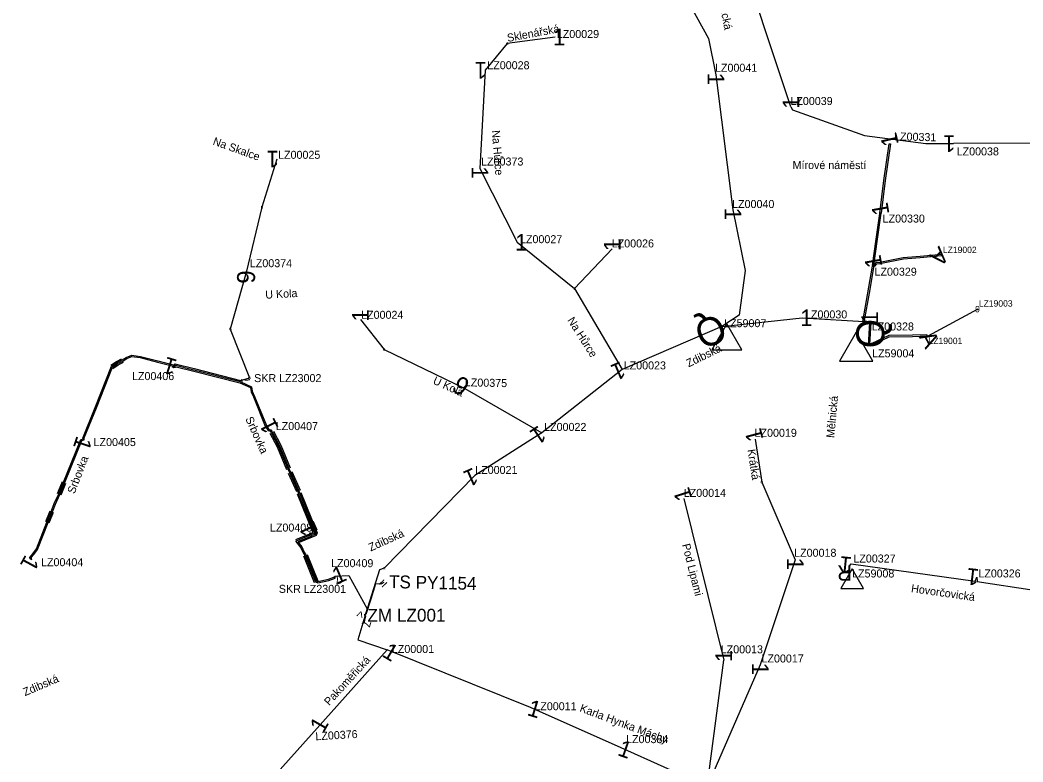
# Model space of a CAD drawing. Extents: x -736540 to -735418, y -1033000 to -1031598.
# Drawn here: x -736325 to -736011.7, y -1032340.8 to -1032109 of the extents above; entities that cross this region are included whole.
import ezdxf

# ---------------------------------------------------------------- set-up
doc = ezdxf.new("R2010")
doc.units = 0
for name, color, linetype in [('ftf_2010', 7, 'Continuous'), ('ftf_2020', 7, 'Continuous'), ('ftf_2050', 7, 'Continuous'), ('ftf_2060', 7, 'Continuous'), ('ftf_2080', 7, 'Continuous'), ('ftf_2140', 7, 'Continuous'), ('ftf_2240', 7, 'Continuous'), ('ftf_3010', 7, 'Continuous'), ('ftf_3010_ftf_3010_gtda_3015_gtda_3015_1', 7, 'Continuous'), ('ftf_3050', 7, 'Continuous'), ('ftf_3050_ftf_3050_gtda_3055_gtda_3055_1', 7, 'Continuous'), ('ftf_3060', 7, 'Continuous'), ('ftf_3060_ftf_3060_gtda_3065_gtda_3065_1', 7, 'Continuous'), ('ftf_3070', 7, 'Continuous'), ('ftf_3070_ftf_3070_gtda_3075_gtda_3075_1', 7, 'Continuous'), ('ftf_3150', 7, 'Continuous'), ('ftf_3150_ftf_3150_gtda_3155_gtda_3155_1', 7, 'Continuous'), ('ftf_3160', 7, 'Continuous'), ('ftf_3160_ftf_3160_gtda_3165_gtda_3165_1', 7, 'Continuous'), ('ftf_3170', 7, 'Continuous'), ('ftf_3170_ftf_3170_gtda_3175_gtda_3175_1', 7, 'Continuous'), ('ftf_3210', 7, 'Continuous'), ('ftf_3240', 7, 'Continuous'), ('ftf_3260', 7, 'Continuous'), ('ftf_3260_ftf_3260_gtda_3265_gtda_3265_1', 7, 'Continuous'), ('ftf_3270', 7, 'Continuous'), ('ftf_3270_ftf_3270_gtda_3275_gtda_3275_1', 7, 'Continuous'), ('ftf_nu', 7, 'Continuous')]:
    doc.layers.add(name, color=color, linetype=linetype)

msp = doc.modelspace()

# ---------------------------------------------------------------- linework, layer by layer
at = {"layer": 'ftf_2010'}
for points in [[(-736084.14, -1032136.1), (-736101.83, -1032082.79)], [(-736127.21, -1032098.34), (-736125.97, -1032099.2), (-736125.31, -1032100.78), (-736117.57, -1032100.74), (-736109.87, -1032114.77), (-736107.59, -1032126.1)], [(-736107.59, -1032126.1), (-736102.25, -1032168.26)], [(-736084.14, -1032136.1), (-736083.63, -1032137.03), (-736061.14, -1032145.09), (-736042.04, -1032147.61), (-736033.38, -1032147.59)], [(-735958.39, -1032137.2), (-735958.85, -1032137.46), (-735959.94, -1032142.82), (-735967.55, -1032142.1), (-735968.5, -1032152.08), (-735972.92, -1032151.65), (-736001.05, -1032147.52), (-736033.38, -1032147.59)], [(-736053.07, -1032147.7), (-736054.74, -1032159.15), (-736056, -1032169.35)], [(-736102.25, -1032168.26), (-736098.43, -1032187.26), (-736100.35, -1032201.22), (-736105.73, -1032204.76)], [(-736058.22, -1032185.7), (-736057.12, -1032177.49), (-736056, -1032169.35)], [(-736058.22, -1032185.7), (-736059.74, -1032194.3), (-736061.27, -1032202.9), (-736059.51, -1032203.25)], [(-736059.34, -1032210.76), (-736059.89, -1032210.72), (-736059.46, -1032203.51), (-736059.51, -1032203.25)], [(-736304.98, -1032240.11), (-736305.39, -1032239.62), (-736301.51, -1032230.04), (-736296.42, -1032217.19), (-736294.7, -1032216), (-736293.07, -1032215.19), (-736291.84, -1032214.41), (-736290.08, -1032213.75), (-736287.38, -1032214.07), (-736281.93, -1032215.51), (-736277.18, -1032216.68), (-736276.97, -1032217.56)], [(-736276.97, -1032217.56), (-736276.77, -1032216.69), (-736276.55, -1032216.42), (-736270.54, -1032217.9), (-736256.06, -1032221.58), (-736253.32, -1032220.8)], [(-736276.97, -1032217.56), (-736276.4, -1032216.87), (-736270.64, -1032218.28), (-736256.19, -1032221.96), (-736252.65, -1032223.55), (-736252.43, -1032224.99), (-736251.73, -1032226.58), (-736248.03, -1032235.72), (-736247.26, -1032236.91), (-736246.67, -1032237.03)], [(-736246.67, -1032237.03), (-736246.78, -1032237.56), (-736246.54, -1032237.86), (-736244.27, -1032242.2), (-736241.33, -1032249.25), (-736240.81, -1032250.37), (-736238.23, -1032256.18), (-736238.05, -1032256.88), (-736233.01, -1032269.24), (-736233.07, -1032269.4), (-736233.62, -1032269.62), (-736234.42, -1032269.21)], [(-736321.33, -1032277.6), (-736321.51, -1032276.96), (-736320.65, -1032275.97), (-736319.52, -1032274.37), (-736316.23, -1032265.98), (-736314.87, -1032262.64), (-736313.93, -1032260.22), (-736312.53, -1032257.21), (-736311.02, -1032253.51), (-736305.7, -1032240.38), (-736304.98, -1032240.11)], [(-736234.42, -1032269.21), (-736234.38, -1032269.94), (-736238.8, -1032271.78), (-736238.82, -1032271.9), (-736237.26, -1032273.84), (-736236.55, -1032275.41), (-736236.06, -1032276.24), (-736232.7, -1032284.52), (-736231.94, -1032284.87), (-736228.53, -1032284.05), (-736226.5, -1032283.37), (-736226.52, -1032282.73)], [(-736211.19, -1032280.26), (-736212.72, -1032280.76), (-736217.01, -1032294.65), (-736217.4, -1032294.8)], [(-736065.77, -1032279.38), (-736065.33, -1032278.91), (-736045.97, -1032281.62), (-736026.61, -1032284.33), (-736026.07, -1032283.1)], [(-736226.52, -1032282.73), (-736222.26, -1032282.58), (-736216.58, -1032292.94), (-736217.05, -1032294.51), (-736217.4, -1032294.8)], [(-736026.07, -1032283.1), (-736025.93, -1032284.39), (-736008.19, -1032287.1), (-735990.46, -1032289.82), (-735986.98, -1032291.47)], [(-736217.4, -1032294.8), (-736217.24, -1032295.33), (-736219.49, -1032302.63), (-736210.28, -1032305.75)]]:
    msp.add_lwpolyline(points, dxfattribs=at)
at = {"layer": 'ftf_2020'}
for points in [[(-736058.22, -1032185.7), (-736057.54, -1032184.73), (-736056.39, -1032184.64), (-736049.06, -1032183.17), (-736043.79, -1032182.77), (-736036.88, -1032182.1)], [(-736059.34, -1032210.76), (-736053.42, -1032207.93), (-736046.17, -1032207.85), (-736043.8, -1032207.79), (-736041.42, -1032207.73)]]:
    msp.add_lwpolyline(points, dxfattribs=at)
at = {"layer": 'ftf_2050'}
for points in [[(-736157.8, -1032114.33), (-736172.83, -1032116.38), (-736179.72, -1032124.69)], [(-736179.72, -1032124.69), (-736181.33, -1032155.34)], [(-736244.72, -1032152.46), (-736249.41, -1032167.46), (-736254.35, -1032187.85)], [(-736181.33, -1032155.34), (-736169.66, -1032178.44)], [(-736169.66, -1032178.44), (-736151.73, -1032192.91), (-736136.87, -1032218.15)], [(-736139.99, -1032180.53), (-736151.73, -1032192.91)], [(-736254.35, -1032187.85), (-736259.29, -1032205.53), (-736253.32, -1032220.8)], [(-736218.63, -1032202.55), (-736211.26, -1032211.91), (-736186.01, -1032224.1), (-736186.05, -1032224.11)], [(-736105.73, -1032204.76), (-736080.61, -1032202.02)], [(-736080.61, -1032202.02), (-736059.51, -1032203.25)], [(-736136.87, -1032218.15), (-736162, -1032237.98)], [(-736186.01, -1032224.1), (-736162, -1032237.98)], [(-736162, -1032237.98), (-736182.91, -1032251.34)], [(-736095.33, -1032239.95), (-736093.27, -1032253.41), (-736082.77, -1032277.61)], [(-736182.91, -1032251.34), (-736211.19, -1032280.26)], [(-736117.59, -1032258.43), (-736105.13, -1032308.95)], [(-736082.77, -1032277.61), (-736093.72, -1032310.39)], [(-736232.21, -1032330.19), (-736210.28, -1032305.75)], [(-736165.48, -1032323.8), (-736210.28, -1032305.75)], [(-736110.31, -1032348.41), (-736105.13, -1032308.95)], [(-736093.72, -1032310.39), (-736110.31, -1032348.41)], [(-736137.15, -1032336.37), (-736165.48, -1032323.8)], [(-736260.81, -1032362.16), (-736232.21, -1032330.19)], [(-736110.31, -1032348.41), (-736137.15, -1032336.37)]]:
    msp.add_lwpolyline(points, dxfattribs=at)
at = {"layer": 'ftf_2060'}
msp.add_lwpolyline([(-736211.38, -1032284.72), (-736212.22, -1032285.28), (-736213.9, -1032285.1), (-736215.4, -1032289.9), (-736216.91, -1032294.69), (-736217.4, -1032294.8), (-736217.04, -1032295.11), (-736217.6, -1032297.43), (-736218.24, -1032297.66)], dxfattribs=at)
at = {"layer": 'ftf_2080'}
for points in [[(-736025.8, -1032199.34), (-736041.42, -1032207.73)], [(-736105.73, -1032204.76), (-736136.87, -1032218.15)]]:
    msp.add_lwpolyline(points, dxfattribs=at)
at = {"layer": 'ftf_2140'}
for points in [[(-736059.51, -1032203.25), (-736059.59, -1032203.64), (-736061.73, -1032203.22), (-736058.65, -1032185.85), (-736058.24, -1032185.72), (-736058.61, -1032185.64), (-736057.52, -1032177.44), (-736056.42, -1032169.43), (-736056, -1032169.35), (-736056.4, -1032169.3), (-736055.13, -1032159.09), (-736053.46, -1032147.65), (-736053.07, -1032147.7)], [(-736058.22, -1032185.7), (-736057.89, -1032185.93), (-736057.32, -1032185.12), (-736056.34, -1032185.03), (-736049.01, -1032183.57), (-736043.76, -1032183.17), (-736037.06, -1032182.52), (-736036.88, -1032182.1)], [(-736041.42, -1032207.73), (-736041.68, -1032207.34), (-736046.18, -1032207.45), (-736053.51, -1032207.53), (-736059.07, -1032210.18), (-736059.34, -1032210.76), (-736059.42, -1032210.35), (-736059.47, -1032210.35), (-736059.05, -1032203.49), (-736059.12, -1032203.17), (-736059.51, -1032203.25)], [(-736321.33, -1032277.6), (-736321.82, -1032277.32), (-736321.95, -1032276.86), (-736320.97, -1032275.72), (-736319.87, -1032274.18), (-736316.6, -1032265.83), (-736315.24, -1032262.49), (-736314.29, -1032260.06), (-736312.89, -1032257.05), (-736311.39, -1032253.36), (-736306, -1032240.06), (-736305.54, -1032240), (-736304.98, -1032240.11), (-736304.93, -1032239.54), (-736301.14, -1032230.19), (-736296.09, -1032217.45), (-736294.5, -1032216.35), (-736292.87, -1032215.54), (-736291.66, -1032214.77), (-736290.03, -1032214.16), (-736287.45, -1032214.47), (-736282.03, -1032215.9), (-736277.51, -1032217.01), (-736277.45, -1032217.26), (-736276.97, -1032217.56), (-736276.41, -1032217.5), (-736276.25, -1032217.32), (-736270.74, -1032218.67), (-736256.32, -1032222.34), (-736253.01, -1032223.83), (-736252.81, -1032225.11), (-736252.1, -1032226.73), (-736248.39, -1032235.91), (-736247.5, -1032237.27), (-736247.14, -1032237.34), (-736246.67, -1032237.03), (-736246.32, -1032237.49), (-736246.21, -1032237.64), (-736243.91, -1032242.03), (-736240.96, -1032249.09), (-736240.44, -1032250.2), (-736237.85, -1032256.04), (-736237.67, -1032256.76), (-736232.58, -1032269.24), (-736232.76, -1032269.7), (-736233.64, -1032270.07), (-736233.98, -1032269.89), (-736233.96, -1032270.2), (-736238.25, -1032271.98), (-736236.92, -1032273.63), (-736236.19, -1032275.22), (-736235.7, -1032276.07), (-736232.39, -1032284.22), (-736231.9, -1032284.45), (-736228.64, -1032283.66), (-736226.96, -1032283.1), (-736226.52, -1032282.73)], [(-736233.98, -1032269.89), (-736234.42, -1032269.21)]]:
    msp.add_lwpolyline(points, dxfattribs=at)
at = {"layer": 'ftf_2240'}
for points in [[(-736108.82, -1032212.03), (-736099.47, -1032212.03), (-736104.14, -1032203.93)], [(-736068.96, -1032215.53), (-736058.57, -1032215.53), (-736063.77, -1032206.53)], [(-736068.57, -1032286.64), (-736061.44, -1032286.64), (-736065.01, -1032280.47)]]:
    msp.add_lwpolyline(points, close=True, dxfattribs=at)
at = {"layer": 'ftf_3210'}
for points in [[(-736296.65, -1032216.86), (-736294.9, -1032215.66), (-736293.24, -1032214.83)], [(-736295.96, -1032217.85), (-736294.29, -1032216.69), (-736292.71, -1032215.91)], [(-736246.9, -1032238.05), (-736244.64, -1032242.37), (-736241.7, -1032249.4)], [(-736245.83, -1032237.49), (-736243.55, -1032241.86), (-736240.59, -1032248.94)], [(-736241.17, -1032250.53), (-736238.6, -1032256.34)], [(-736240.07, -1032250.05), (-736237.5, -1032255.85)], [(-736313.27, -1032256.91), (-736311.76, -1032253.21)], [(-736312.16, -1032257.36), (-736310.65, -1032253.66)], [(-736237.31, -1032256.58), (-736232.15, -1032269.24), (-736232.45, -1032270), (-736233.69, -1032270.52)], [(-736238.42, -1032257.03), (-736233.49, -1032269.14), (-736233.78, -1032269.26)], [(-736316.97, -1032265.68), (-736315.61, -1032262.34)], [(-736315.86, -1032266.13), (-736314.5, -1032262.79)], [(-736234.52, -1032269.57), (-736238.95, -1032271.41)], [(-736233.69, -1032270.52), (-736237.75, -1032272.21)], [(-736236.43, -1032276.39), (-736233.08, -1032284.67)], [(-736235.32, -1032275.94), (-736231.96, -1032284.21)]]:
    msp.add_lwpolyline(points, dxfattribs=at)

# ---------------------------------------------------------------- texts
at = {"layer": 'ftf_3010'}
for p in [(-736158.45, -1032116.93), (-736170.31, -1032181.04), (-736081.26, -1032204.62)]:
    msp.add_text('1', height=5.2, dxfattribs=at).set_placement(p)
for rotation, p in [(180, (-736179.07, -1032122.09)), (270, (-736110.19, -1032125.45)), (90, (-736081.54, -1032136.75)), (103.2874, (-736050.39, -1032147.74)), (180, (-736032.73, -1032144.99)), (180, (-736244.07, -1032149.86)), (270, (-736183.93, -1032154.69)), (270, (-736104.85, -1032167.62)), (99.9677, (-736053.33, -1032169.53)), (90, (-736137.39, -1032181.18)), (99.7752, (-736055.54, -1032185.9)), (90, (-736216.03, -1032203.2)), (90, (-736056.91, -1032203.89)), (162.6923, (-736275.58, -1032215.27)), (203.0185, (-736137.29, -1032215.51)), (116.5555, (-736244.05, -1032236.44)), (213.7482, (-736162.91, -1032235.46)), (104.7548, (-736092.66, -1032239.91)), (251.6061, (-736307.24, -1032238.67)), (203.5236, (-736183.36, -1032248.7)), (107.648, (-736114.92, -1032258.26)), (113.88, (-736231.78, -1032268.75)), (241.6081, (-736323.3, -1032275.79)), (270, (-736085.37, -1032276.97)), (174.0995, (-736064.86, -1032276.86)), (23.1325, (-736226.09, -1032285.38)), (173.5145, (-736025.13, -1032280.59)), (329.4296, (-736212.16, -1032307.66)), (90, (-736102.53, -1032309.6)), (270, (-736096.32, -1032309.75)), (342.96, (-736166.86, -1032326.09)), (60.407, (-736230.27, -1032332.04)), (340.8983, (-736138.61, -1032338.62))]:
    msp.add_text('1', height=5.2, rotation=rotation, dxfattribs=at).set_placement(p)
at = {"layer": 'ftf_3010_ftf_3010_gtda_3015_gtda_3015_1'}
for s, p in [('LZ00029', (-736157.28, -1032114.63)), ('LZ00330', (-736055.5, -1032172.28)), ('LZ00027', (-736168.79, -1032178.72)), ('LZ00329', (-736058.03, -1032188.88)), ('LZ00030', (-736079.75, -1032202.22)), ('LZ00328', (-736058.92, -1032205.99)), ('LZ00406', (-736290.01, -1032221.49)), ('LZ00407', (-736245.1, -1032237.11)), ('LZ00405', (-736302.01, -1032242.1)), ('LZ00408', (-736246.91, -1032268.81)), ('LZ00404', (-736318.43, -1032279.63)), ('LZ00409', (-736227.8, -1032279.93)), ('LZ00327', (-736064.64, -1032278.48)), ('LZ00326', (-736025.58, -1032283.14)), ('LZ00011', (-736164.31, -1032324.63)), ('LZ00384', (-736135.64, -1032334.9))]:
    msp.add_text(s, height=2.5, dxfattribs=at).set_placement(p)
for s, rotation, p in [('LZ00028', 0, (-736179.01, -1032124.38)), ('LZ00041', 0, (-736107.87, -1032125.16)), ('LZ00039', 0, (-736084.32, -1032135.56)), ('LZ00331', 358.7101, (-736051.93, -1032146.59)), ('LZ00025', 0, (-736244.37, -1032152.36)), ('LZ00038', 0, (-736032.37, -1032151.3)), ('LZ00373', 0, (-736180.93, -1032154.46)), ('LZ00040', 0, (-736102.52, -1032167.73)), ('LZ00026', 0, (-736140.13, -1032180.05)), ('LZ00024', 0, (-736218.42, -1032202.34)), ('LZ00023', 0, (-736136.39, -1032218.15)), ('LZ00022', 0, (-736161.25, -1032237.37)), ('LZ00019', 0, (-736095.5, -1032239.21)), ('LZ00021', 0, (-736182.78, -1032250.81)), ('LZ00014', 0, (-736117.62, -1032257.97)), ('LZ00018', 0, (-736083.13, -1032276.68)), ('LZ00001', 0, (-736208.82, -1032306.74)), ('LZ00013', 0, (-736106.08, -1032306.84)), ('LZ00017', 0, (-736093.34, -1032309.71)), ('LZ00376', 3.2234, (-736232.64, -1032334.02))]:
    msp.add_text(s, height=2.5, rotation=rotation, dxfattribs=at).set_placement(p)
at = {"layer": 'ftf_3050'}
for rotation, p in [(270, (-736257.19, -1032187.18)), (146.9948, (-736183.93, -1032222.09))]:
    msp.add_text('6', height=5.63, rotation=rotation, dxfattribs=at).set_placement(p)
at = {"layer": 'ftf_3050_ftf_3050_gtda_3055_gtda_3055_1'}
for s, rotation, p in [('LZ00374', 0, (-736253.19, -1032186.22)), ('LZ00375', 358.7843, (-736186.04, -1032223.42))]:
    msp.add_text(s, height=2.5, rotation=rotation, dxfattribs=at).set_placement(p)
at = {"layer": 'ftf_3060'}
for rotation, p in [(223.6117, (-736037.84, -1032179.42)), (298.3564, (-736044.25, -1032207.96))]:
    msp.add_text('A', height=5.2, rotation=rotation, dxfattribs=at).set_placement(p)
at = {"layer": 'ftf_3060_ftf_3060_gtda_3065_gtda_3065_1'}
for s, rotation, p in [('LZ19002', 0.1256, (-736036.67, -1032181.82)), ('LZ19001', 359.7064, (-736041.16, -1032210.21))]:
    msp.add_text(s, height=2, rotation=rotation, dxfattribs=at).set_placement(p)
at = {"layer": 'ftf_3070'}
msp.add_text('9', height=2, dxfattribs=at).set_placement((-736026.6, -1032200.34))
at = {"layer": 'ftf_3070_ftf_3070_gtda_3075_gtda_3075_1'}
msp.add_text('LZ19003', height=2, dxfattribs=at).set_placement((-736025.44, -1032198.54))
at = {"layer": 'ftf_3150'}
msp.add_text('>', height=2.7, rotation=70.7877, dxfattribs=at).set_placement((-736217.84, -1032296.07))
at = {"layer": 'ftf_3150_ftf_3150_gtda_3155_gtda_3155_1'}
msp.add_text('ZM LZ001', height=4, rotation=0.0569, dxfattribs=at).set_placement((-736216.43, -1032296.95))
at = {"layer": 'ftf_3160'}
msp.add_text('=', height=3.3, rotation=44.8776, dxfattribs=at).set_placement((-736211.38, -1032287.05))
at = {"layer": 'ftf_3160_ftf_3160_gtda_3165_gtda_3165_1'}
msp.add_text('TS PY1154', height=4, rotation=358.7185, dxfattribs=at).set_placement((-736209.76, -1032286.45))
at = {"layer": 'ftf_3170'}
for rotation, p in [(110.3032, (-736252.85, -1032222.06)), (199.6962, (-736225.25, -1032282.27)), (253.6169, (-736217.78, -1032296.23))]:
    msp.add_text('7', height=2.7, rotation=rotation, dxfattribs=at).set_placement(p)
at = {"layer": 'ftf_3170_ftf_3170_gtda_3175_gtda_3175_1'}
for s, p in [('SKR LZ23002', (-736251.84, -1032222.12)), ('SKR LZ23001', (-736244.13, -1032287.95))]:
    msp.add_text(s, height=2.5, dxfattribs=at).set_placement(p)
at = {"layer": 'ftf_3240'}
for p in [(-736173.23, -1032116.78), (-736249.81, -1032167.86), (-736152.13, -1032193.31), (-736259.69, -1032205.93), (-736211.66, -1032212.31), (-736253.72, -1032221.2), (-736093.67, -1032253.81), (-736211.59, -1032280.66)]:
    msp.add_text('G', height=0.8, dxfattribs=at).set_placement(p)
at = {"layer": 'ftf_3260'}
for rotation, p in [(203.0215, (-736106.73, -1032200.41)), (90, (-736054.94, -1032211.54))]:
    msp.add_text('Q', height=8.8, rotation=rotation, dxfattribs=at).set_placement(p)
at = {"layer": 'ftf_3260_ftf_3260_gtda_3265_gtda_3265_1'}
msp.add_text('LZ59007', height=2.5, dxfattribs=at).set_placement((-736105.02, -1032204.96))
msp.add_text('LZ59004', height=2.5, rotation=0, dxfattribs=at).set_placement((-736058.78, -1032214.38))
at = {"layer": 'ftf_3270'}
msp.add_text('R', height=4.8, rotation=180, dxfattribs=at).set_placement((-736065.07, -1032279.38))
at = {"layer": 'ftf_3270_ftf_3270_gtda_3275_gtda_3275_1'}
msp.add_text('LZ59008', height=2.5, dxfattribs=at).set_placement((-736065.04, -1032283.15))
at = {"layer": 'ftf_nu'}
for s, rotation, p in [('Mělnická', 281.1659, (-736107.45, -1032099.28)), ('Sklenářská', 10.5891, (-736172.59, -1032115.87)), ('Na Hůrce', 274.5703, (-736177.6, -1032143.53)), ('Na Skalce', 340.3831, (-736264.94, -1032147.88)), ('U Kola', 3.2547, (-736248.3, -1032196.09)), ('Na Hůrce', 302.4143, (-736154.1, -1032202.78)), ('Zdibská', 26.1415, (-736116.1, -1032217.53)), ('U Kola', 335.4074, (-736196.21, -1032222.52)), ('Mělnická', 84.8145, (-736070.61, -1032239.65)), ('Srbovka', 294.1258, (-736254.65, -1032233.57)), ('Krátká', 278.7559, (-736097.75, -1032243.26)), ('Srbovka', 68.9149, (-736307.98, -1032257.22)), ('Zdibská', 24.2618, (-736215.42, -1032275.05)), ('Pod Lipami', 284.1727, (-736118.16, -1032272.91)), ('Hovorčovická', 351.9516, (-736046.71, -1032287.73)), ('Pakoměřická', 47.3968, (-736228.41, -1032323.34)), ('Zdibská', 23.0224, (-736323.42, -1032320.24)), ('Karla Hynka Máchy', 339.529, (-736150.34, -1032324.93))]:
    msp.add_text(s, height=2.5, rotation=rotation, dxfattribs=at).set_placement(p)
msp.add_text('Mírové náměstí', height=2.5, dxfattribs=at).set_placement((-736083.62, -1032155.57))

doc.saveas('drawing.dxf')
